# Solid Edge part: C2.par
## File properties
Author: edge
Template: Jis Part.par
Last saved by: edge
Revision: 3
Application: Solid Edge
Username: edge
文書内容のタイプ: 0
Accuracy: 0.990
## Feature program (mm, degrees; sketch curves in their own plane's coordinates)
sketch for "unnamed Protrusion 1" plane through (0, 0, 0) normal (0, 0, 1) x-axis (1, 0, 0)
  circle centre (0, 0) radius 30
  dimension = 0.0001
extrude "unnamed Protrusion 1" add finite 100 along +normal
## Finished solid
Body 1: solid body, 3 faces, 2 edges, 0 vertices.
  Faces by surface: plane 2, cylinder 1
  Edges by curve: circle 2
Bounding box of the edges (mm): 60.000 x 60.000 x 100.000, from (-30, -30, 0) to (30, 30, 100).
Cylindrical faces by radius (mm): R30 x1
Planar faces by outward normal: +z 1, -z 1
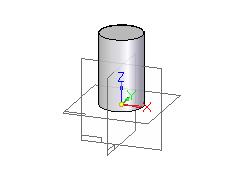
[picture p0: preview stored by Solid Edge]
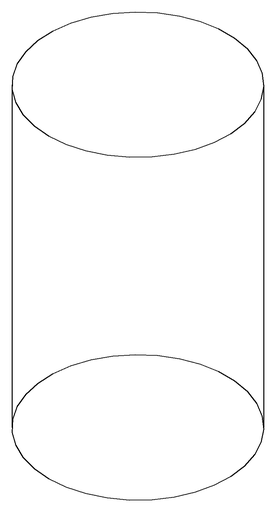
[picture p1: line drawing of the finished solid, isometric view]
